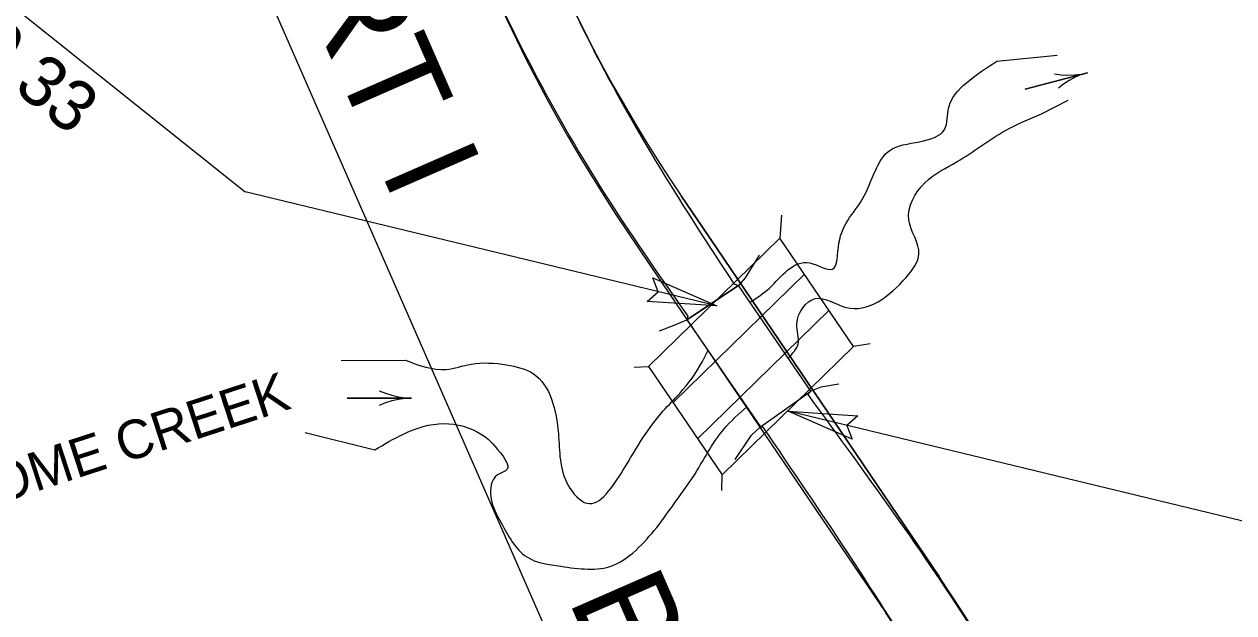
# Model space of a CAD drawing. Extents: x 1730256 to 1738218, y 910410 to 917906.
# Drawn here: x 1735145.7 to 1735520.4, y 915522.8 to 915705.2 of the extents above; entities that cross this region are included whole.
import ezdxf

# ---------------------------------------------------------------- set-up
doc = ezdxf.new("R2010")
doc.units = 0
for name, color, linetype in [('Default', 7, 'Continuous'), ('Old_Level_23', 7, 'Continuous'), ('Old_Level_3', 7, 'Continuous'), ('Old_Level_5', 7, 'Continuous'), ('Old_Level_7', 7, 'Continuous'), ('Prop DSN Text', 7, 'Continuous'), ('Prop EOT', 7, 'Continuous'), ('Prop Roadway Culvert', 7, 'Continuous'), ('Prop Shade Light', 7, 'Continuous')]:
    doc.layers.add(name, color=color, linetype=linetype)

# ---------------------------------------------------------------- blocks, each defined once
blk = doc.blocks.new('EXIST HYDRO RIVER FLOW ARROW')
at = {"layer": 'Default'}
blk.add_line((0, 0), (0, 0), dxfattribs=at)
blk.add_lwpolyline([(0, 0.04575), (0.03775, 0.03), (0.07725, 0.01725), (0.118, 0.00775), (0.159, 0.0015), (0.2, 0), (-0.2, 0), (0.2, 0), (0.159, -0.0015), (0.118, -0.00775), (0.07725, -0.01725), (0.03775, -0.03), (0, -0.04575)], dxfattribs=at)

msp = doc.modelspace()

# ---------------------------------------------------------------- linework, layer by layer
at = {"layer": 'Old_Level_23'}
msp.add_line((1735146.86, 915884), (1735391.91, 915324.39), dxfattribs=at)
at = {"layer": 'Old_Level_3'}
for points in [[(1735350.95, 915613.53), (1735366.96, 915624.2)], [(1735365.49, 915624.75), (1735366.96, 915624.2)], [(1735351.32, 915614.71), (1735350.95, 915613.53)], [(1735373.79, 915580.41), (1735389.4, 915591.43)], [(1735389.4, 915591.43), (1735388.43, 915590.42)], [(1735373.79, 915580.41), (1735374.46, 915580.41)]]:
    msp.add_lwpolyline(points, dxfattribs=at)
for points in [[(1735242.69, 915948.94), (1735247.35, 915903.38), (1735252.28, 915860.46), (1735259.33, 915816.86), (1735270.45, 915772.23), (1735284.64, 915731.05), (1735303.25, 915691.23), (1735326.98, 915650.38), (1735351.32, 915614.71)], [(1735285.1, 915791.17), (1735288.52, 915779.54), (1735302.56, 915739.9), (1735320.07, 915701.16), (1735342.82, 915660.37), (1735365.49, 915624.75)], [(1735388.43, 915590.42), (1735416.78, 915551.19), (1735441.77, 915513.78), (1735465.3, 915471.57), (1735485.01, 915425.76), (1735499.55, 915381.43), (1735512.09, 915334.5), (1735524.18, 915290.01), (1735536.56, 915251.67), (1735553.3, 915211.16), (1735574.05, 915173.58), (1735599.55, 915136.89), (1735628.53, 915103.19), (1735661.79, 915070.16), (1735681.36, 915051.5)], [(1735374.46, 915580.41), (1735401.37, 915540.39), (1735425.26, 915502.31), (1735446.73, 915462.77), (1735465.76, 915420.2), (1735480.61, 915373.81), (1735493.26, 915327.98), (1735505.79, 915283.89), (1735518.61, 915242.74), (1735535.21, 915202.71), (1735557.35, 915162.87), (1735584.25, 915124.34), (1735613.79, 915089.74), (1735647.95, 915055.56), (1735667.73, 915036.98)]]:
    msp.add_spline(points, degree=3, dxfattribs=at)
at = {"layer": 'Old_Level_5'}
for p, q in [((1735366.96, 915624.2), (1735350.95, 915613.53)), ((1735389.4, 915591.43), (1735366.96, 915624.2)), ((1735350.95, 915613.53), (1735373.79, 915580.41)), ((1735373.79, 915580.41), (1735389.4, 915591.43))]:
    msp.add_line(p, q, dxfattribs=at)
for points in [[(1735373.39, 915633.67), (1735369.03, 915626.64), (1735366.96, 915624.2)], [(1735342.55, 915610.17), (1735347.08, 915611.94), (1735350.95, 915613.53)], [(1735398.06, 915593.6), (1735392.53, 915592.66), (1735389.4, 915591.43)], [(1735365.97, 915570.32), (1735370.98, 915577.82), (1735373.79, 915580.41)]]:
    msp.add_lwpolyline(points, dxfattribs=at)
at = {"layer": 'Old_Level_7'}
for p, q in [((1735447.01, 915693.74), (1735465.68, 915695.64)), ((1735460.89, 915677.41), (1735469.09, 915681.67)), ((1735243.86, 915600.97), (1735263.86, 915601.03)), ((1735232.73, 915578.61), (1735254.31, 915573.28))]:
    msp.add_line(p, q, dxfattribs=at)
for points in [[(1735370.51, 915619.01), (1735376.56, 915623.42), (1735389.05, 915631.23), (1735396.05, 915629.25), (1735398.09, 915637.34), (1735405.94, 915651.97), (1735413.84, 915666.08), (1735423.1, 915668.77), (1735430.81, 915672.61), (1735432.1, 915679.44), (1735437.52, 915686.96), (1735447.01, 915693.74)], [(1735382.37, 915601.69), (1735385.46, 915606.16), (1735385.05, 915612.36), (1735390.73, 915620.14), (1735400.25, 915617.44), (1735418.91, 915626.73), (1735422.88, 915634.01), (1735419.76, 915644.55), (1735424.68, 915656.02), (1735434.67, 915662.61), (1735449.5, 915672.16), (1735460.89, 915677.41)], [(1735263.86, 915601.03), (1735276.4, 915598.23), (1735284.12, 915599.82), (1735295.15, 915599.62), (1735303.43, 915596.87), (1735311.17, 915578.39), (1735314.21, 915562.34), (1735320.03, 915556.72), (1735331.19, 915566.93), (1735343.69, 915585.34), (1735348.78, 915590.78), (1735355.8, 915600.66), (1735357.53, 915604)], [(1735254.31, 915573.28), (1735263.2, 915578.17), (1735275.77, 915581.42), (1735287.08, 915578.28), (1735293.1, 915572.48), (1735295.28, 915567.28), (1735292.35, 915565.49), (1735290.24, 915558.68), (1735293.44, 915550.63), (1735301.37, 915540.1), (1735311.9, 915537.19), (1735328.09, 915537.45), (1735336.03, 915542.97), (1735347.99, 915557.89), (1735352.94, 915564.92), (1735362.5, 915579.75), (1735369.53, 915586.59)]]:
    msp.add_spline(points, degree=3, dxfattribs=at)
at = {"layer": 'Prop DSN Text'}
for p, q in [((1734996.62, 915827.33), (1735214.11, 915653.28)), ((1735360.24, 915617.91), (1735214.11, 915653.28)), ((1735576.12, 915538.35), (1735382.35, 915585.25))]:
    msp.add_line(p, q, dxfattribs=at)
for points in [[(1735340.43, 915626.55), (1735360.24, 915617.91), (1735338.67, 915619.29), (1735342.09, 915622.3)], [(1735402.17, 915576.61), (1735382.35, 915585.25), (1735403.93, 915583.87), (1735400.51, 915580.85)]]:
    msp.add_lwpolyline(points, close=True, dxfattribs=at)
at = {"layer": 'Prop EOT'}
for p, q in [((1735349.2, 915652.05), (1735356.02, 915641.98)), ((1735332.64, 915640.84), (1735339.46, 915630.77)), ((1735356.02, 915641.98), (1735429.14, 915533.98)), ((1735339.46, 915630.77), (1735412.58, 915522.77))]:
    msp.add_line(p, q, dxfattribs=at)
for centre, radius, start, end in [((1735734.25, 915912.74), 485, 188.0669, 214.0997), ((1735734.25, 915912.74), 465, 188.0669, 214.0997), ((1735006.83, 915248.06), 510, 17.8738, 34.0997), ((1735006.83, 915248.06), 490, 17.8738, 34.0997)]:
    msp.add_arc(centre, radius, start, end, dxfattribs=at)
at = {"layer": 'Prop Roadway Culvert'}
for p, q in [((1735380.33, 915646.03), (1735379.82, 915638.94)), ((1735379.82, 915638.94), (1735339.13, 915599.15)), ((1735402.6, 915605.28), (1735379.82, 915638.94)), ((1735387.41, 915627.73), (1735346.72, 915587.94)), ((1735395.01, 915616.5), (1735354.32, 915576.71)), ((1735361.92, 915565.49), (1735402.6, 915605.28)), ((1735407.79, 915606.18), (1735402.6, 915605.28)), ((1735334.65, 915598.93), (1735339.13, 915599.15)), ((1735339.13, 915599.15), (1735361.92, 915565.49)), ((1735361.8, 915560.66), (1735361.92, 915565.49))]:
    msp.add_line(p, q, dxfattribs=at)
at = {"layer": 'Prop Shade Light'}
for p, q in [((1735356.02, 915641.98), (1735349.2, 915652.05)), ((1735332.64, 915640.84), (1735339.46, 915630.77)), ((1735429.14, 915533.98), (1735356.02, 915641.98)), ((1735339.46, 915630.77), (1735412.58, 915522.77))]:
    msp.add_line(p, q, dxfattribs=at)
for centre, radius, start, end in [((1735734.25, 915912.74), 485, 188.0669, 214.0997), ((1735734.25, 915912.74), 465, 188.0669, 214.0997), ((1735006.83, 915248.06), 510, 17.8738, 34.0997), ((1735006.83, 915248.06), 490, 17.8738, 34.0997)]:
    msp.add_arc(centre, radius, start, end, dxfattribs=at)

# ---------------------------------------------------------------- block references
at = {"layer": 'Old_Level_7', "xscale": 49.99999999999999, "yscale": 50, "rotation": 14.84313494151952}
msp.add_blockref('EXIST HYDRO RIVER FLOW ARROW', (1735465.48, 915687.61), dxfattribs=at)
at = {"layer": 'Old_Level_7', "xscale": 50, "yscale": 50}
msp.add_blockref('EXIST HYDRO RIVER FLOW ARROW', (1735255.71, 915589.32), dxfattribs=at)

# ---------------------------------------------------------------- texts
at = {"layer": 'Old_Level_23'}
msp.add_text('PART I            B-4864', height=30, rotation=293.6484, dxfattribs=at).set_placement((1735208.57, 915768.01))
at = {"layer": 'Old_Level_7'}
msp.add_text('TROUBLESOME CREEK ', height=12, rotation=18.0511, dxfattribs=at).set_placement((1735055.07, 915529.56))
at = {"layer": 'Prop DSN Text'}
for s, height, p in [('BEGIN TIP PROJECT B-4864', 28, (1735380.83, 915979.55)), ('-L- POT STA. 16+00.33', 15.75, (1734987.12, 915809))]:
    msp.add_text(s, height=height, rotation=321.3297, dxfattribs=at).set_placement(p)

doc.saveas('drawing.dxf')
